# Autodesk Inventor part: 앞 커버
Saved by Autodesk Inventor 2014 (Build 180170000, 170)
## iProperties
Created: 2026-06
Part Number: 앞 커버
Material: 일반
Document SubType Name: Modeling
Designer: dg
Density: 1 g/cm^3
Appearance: 기본값
Author: dg
Author: jhkim
Creation Date: 2026-05-29
Sending System: Autodesk Inventor 2027
Preprocessor: ST-DEVELOPER v20.1
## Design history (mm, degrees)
node "앞 커버1"
node "솔리드1"
node "기준1"
